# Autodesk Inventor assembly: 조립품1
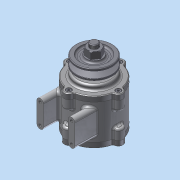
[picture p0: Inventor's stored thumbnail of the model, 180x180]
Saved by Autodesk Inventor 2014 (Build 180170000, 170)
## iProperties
Created: 2015-03
Part Number: 조립품1
Document SubType Name: Assembly
Designer: net
Author: net
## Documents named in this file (11)
- C:\Users\net\Desktop\450305v1048\조립품1.iam
- C:\Users\net\Desktop\450305v1048\1.본체.ipt
- C:\Users\net\Desktop\450305v1048\커버.ipt
- C:\Users\net\Desktop\450305v1048\커버2.ipt
- C:\Users\net\Desktop\450305v1048\베어링 6204.ipt
- C:\Users\net\Desktop\450305v1048\축.ipt
- C:\Users\net\Desktop\450305v1048\오일실.ipt
- C:\Users\net\Desktop\450305v1048\M 4 x 12.ipt
- C:\Users\net\Desktop\450305v1048\키(4 x 4 x 12).ipt
- C:\Users\net\Desktop\450305v1048\V벨트풀리.ipt
- C:\Users\net\Desktop\450305v1048\너트 M12x1.25.ipt
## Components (15 placed, 7 different names)
1. 1.본체:1
2. KS B 2023 6204 - 20 x 47 x 14:1
3. KS B 2023 6204 - 20 x 47 x 14:2
4. KS B 2804 D D - 20 32 8:1
5. KS B 1311 (I) 4 x 4 x 12:1 — 각도:1, 각도:2
6. 그루브 풀리1:1 — 각도:2
7. KS B 1012 클래스 1 일반 - 미터 M12x1.25:1
8. KS B 1003 - 미터 M 4 x 12:2
9. KS B 1003 - 미터 M 4 x 12:3
10. KS B 1003 - 미터 M 4 x 12:4
11. KS B 1003 - 미터 M 4 x 12:5
12. KS B 1003 - 미터 M 4 x 12:1
13. KS B 1003 - 미터 M 4 x 12:6
14. KS B 1003 - 미터 M 4 x 12:7
15. KS B 1003 - 미터 M 4 x 12:8
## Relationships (2: Angle 2)
- 각도:1 [Angle]: KS B 1311 (I) 4 x 4 x 12:1
- 각도:2 [Angle]: KS B 1311 (I) 4 x 4 x 12:1 ↔ 그루브 풀리1:1
